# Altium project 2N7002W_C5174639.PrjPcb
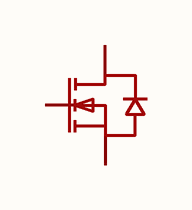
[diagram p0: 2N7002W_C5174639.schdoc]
1 sheet, 1 parts. Net scope: global (net labels, ports and power ports of the same name join across sheets).

## Sheet 2N7002W_C5174639.schdoc
size 127 x 101 mm

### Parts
Q?  2n7002w_c5174639  [SOT-323-3_L2.1-W1.3-P1.30-LS2.3-BR]  (value not drawn)

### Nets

Not connected (* = marked no-connect by the designer): Q? 1(G) 2(S) 3(D)

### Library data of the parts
Q? = 2n7002w_c5174639: 数量:1个N沟道;漏源电压(Vdss):60V;连续漏极电流(Id):200mA;导通电阻(RDS(on)):1.6Ω@10V;耗散功率(Pd):156mW;阈值电压(Vgs(th)):2V;; Manufacturer: MSKSEMI(美森科); AddInBom: yes; ModelId: 81bbbbdf3145418d8c918b8f2fd0a837; ModelTransform: 90.551,78.74,0,0,0,0,0,0,0; Number: 1个N沟道; Drain to Source Voltage: 60V; Current - Continuous Drain(Id): 200mA; Pd - Power Dissipation: 156mW; Gate Threshold Voltage (Vgs(th)): 2V; Gate Charge(Qg): 2nC@10V; Input Capacitance(Ciss): 25pF; Reverse Transfer Capacitance (Crss@Vds): 6.8pF; Output Capacitance(Coss): 15pF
